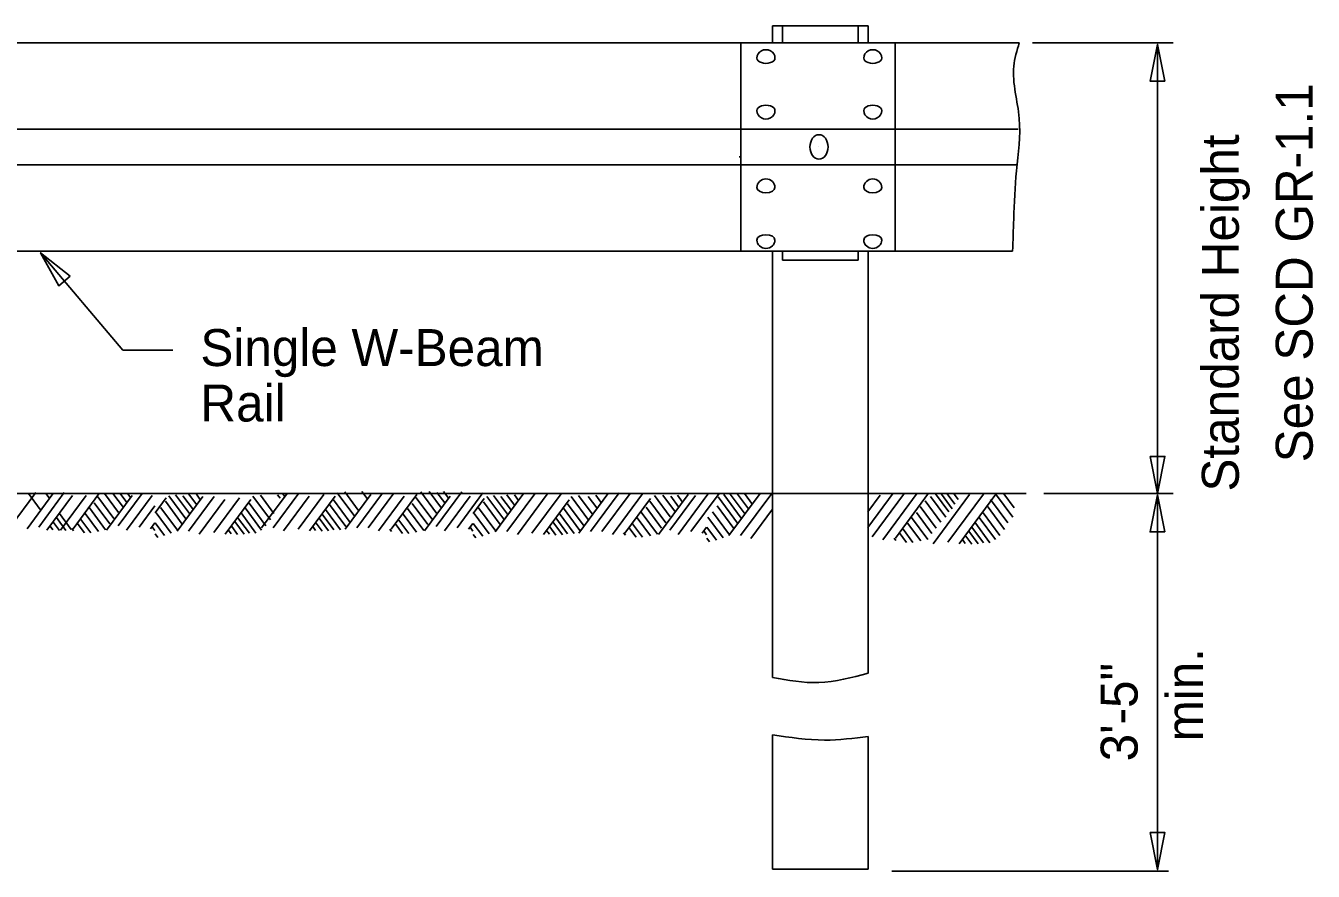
# Model space of a CAD drawing. Extents: x 0 to 34, y 0 to 22.
# Drawn here: x 18.561 to 23.437, y 8.943 to 12.146 of the extents above; entities that cross this region are included whole.
import ezdxf

# ---------------------------------------------------------------- set-up
doc = ezdxf.new("R2010")
doc.units = 0
doc.layers.add('ST_Details', color=7, linetype='Continuous')
doc.layers.add('ST_Text', color=7, linetype='Continuous')

msp = doc.modelspace()

# ---------------------------------------------------------------- linework, layer by layer
at = {"layer": 'ST_Details'}
for p, q in [((21.3896, 12.1461), (21.752, 12.1461)), ((21.3896, 12.0829), (21.3896, 12.1461)), ((21.4275, 12.1461), (21.4275, 12.0817)), ((21.7132, 12.1461), (21.7132, 12.0837)), ((21.752, 12.0837), (21.752, 12.1461)), ((14.5458, 12.0817), (21.8542, 12.0817)), ((21.2687, 11.2925), (21.2687, 12.0817)), ((21.8542, 11.2925), (21.8542, 12.0817)), ((21.8542, 12.0817), (22.3238, 12.0817)), ((15.1987, 11.7547), (21.2687, 11.7547)), ((21.2672, 11.7547), (22.3191, 11.7547)), ((21.5651, 11.687), (21.5651, 11.687)), ((15.1987, 11.6192), (21.2687, 11.6192)), ((21.2665, 11.6492), (21.2626, 11.6492)), ((21.2672, 11.6192), (22.3147, 11.6192)), ((15.1987, 11.2925), (21.8542, 11.2925)), ((21.3896, 11.2928), (21.3896, 10.3748)), ((21.4275, 11.2925), (21.4275, 11.2581)), ((21.7132, 11.2925), (21.7132, 11.2581)), ((21.752, 11.2925), (21.752, 10.3748)), ((21.8542, 11.2925), (22.2984, 11.2925)), ((21.4275, 11.2581), (21.7132, 11.2581)), ((21.752, 10.3748), (18.3908, 10.3748)), ((18.5023, 10.2463), (18.5994, 10.3778)), ((18.5661, 10.241), (18.6631, 10.3724)), ((18.6155, 10.3138), (18.5706, 10.3748)), ((18.6097, 10.2463), (18.7067, 10.3778)), ((18.6492, 10.3579), (18.6369, 10.3748)), ((18.6409, 10.2356), (18.7382, 10.3671)), ((18.6927, 10.2356), (18.7899, 10.3671)), ((18.7402, 10.241), (18.8374, 10.3724)), ((18.8788, 10.2594), (18.8202, 10.3388)), ((18.8949, 10.2796), (18.8342, 10.3617)), ((18.912, 10.3025), (18.8586, 10.3748)), ((18.867, 10.2356), (18.9641, 10.3671)), ((18.931, 10.3207), (18.891, 10.3748)), ((18.9106, 10.2518), (19.0014, 10.3748)), ((18.9431, 10.3406), (18.9179, 10.3748)), ((18.9422, 10.2356), (19.0392, 10.3671)), ((18.9585, 10.3579), (18.946, 10.3748)), ((19.0509, 10.3007), (19.0928, 10.3573)), ((19.1531, 10.2587), (19.0897, 10.3448)), ((19.1667, 10.2787), (19.1024, 10.3658)), ((19.1807, 10.2979), (19.1277, 10.3695)), ((19.1343, 10.2312), (19.2313, 10.3627)), ((19.1955, 10.3122), (19.1561, 10.3658)), ((19.1778, 10.2312), (19.275, 10.3627)), ((19.2075, 10.3324), (19.1785, 10.3715)), ((19.2229, 10.3496), (19.2069, 10.3715)), ((19.2175, 10.2206), (19.3146, 10.3519)), ((19.2728, 10.2261), (19.3699, 10.3573)), ((19.3165, 10.2206), (19.4135, 10.3519)), ((19.4878, 10.274), (19.4214, 10.3638)), ((19.5004, 10.2989), (19.4496, 10.3677)), ((19.454, 10.244), (19.5505, 10.3748)), ((19.4975, 10.244), (19.5947, 10.3754)), ((19.5241, 10.3567), (19.5145, 10.3695)), ((19.5426, 10.3623), (19.5334, 10.3748)), ((19.537, 10.2333), (19.6342, 10.3647)), ((19.5927, 10.2387), (19.6896, 10.3702)), ((19.636, 10.2333), (19.7332, 10.3647)), ((19.7897, 10.2647), (19.727, 10.3497)), ((19.8074, 10.2867), (19.7409, 10.3767)), ((19.8202, 10.3117), (19.7692, 10.3805)), ((19.7707, 10.2387), (19.8677, 10.3702)), ((19.8143, 10.244), (19.9114, 10.3754)), ((19.8539, 10.3557), (19.8342, 10.3823)), ((19.8579, 10.244), (19.9549, 10.3754)), ((19.8974, 10.2333), (19.9945, 10.3647)), ((19.9449, 10.2387), (20.042, 10.3702)), ((20.0997, 10.2772), (20.0387, 10.3595)), ((20.1167, 10.3002), (20.0571, 10.3805)), ((20.0717, 10.2333), (20.1687, 10.3647)), ((20.1357, 10.3183), (20.0884, 10.3823)), ((20.1153, 10.2493), (20.2122, 10.3808)), ((20.1477, 10.3383), (20.118, 10.3785)), ((20.1632, 10.3557), (20.1433, 10.3823)), ((20.147, 10.2333), (20.2439, 10.3647)), ((20.1943, 10.244), (20.2925, 10.3767)), ((20.2554, 10.2982), (20.2974, 10.3551)), ((20.3577, 10.2565), (20.2942, 10.3424)), ((20.3713, 10.2765), (20.3071, 10.3635)), ((20.3852, 10.2956), (20.3325, 10.3672)), ((20.3389, 10.2289), (20.4477, 10.3761)), ((20.3395, 10.2297), (20.4359, 10.3603)), ((20.4001, 10.3099), (20.3607, 10.3635)), ((20.3831, 10.2297), (20.4885, 10.3724)), ((20.4122, 10.3301), (20.3832, 10.3692)), ((20.4276, 10.3472), (20.4114, 10.3692)), ((20.4227, 10.219), (20.5352, 10.3713)), ((20.4782, 10.2245), (20.5881, 10.3734)), ((20.5215, 10.219), (20.6187, 10.3503)), ((20.693, 10.2724), (20.6266, 10.3623)), ((20.7057, 10.2973), (20.6547, 10.3662)), ((20.6562, 10.2245), (20.7657, 10.3726)), ((20.7237, 10.3195), (20.6915, 10.3631)), ((20.6999, 10.2297), (20.8087, 10.377)), ((20.7394, 10.3413), (20.7197, 10.368)), ((20.7433, 10.2297), (20.8499, 10.3738)), ((20.7829, 10.219), (20.8963, 10.3724)), ((20.8304, 10.2245), (20.9275, 10.3557)), ((20.9851, 10.2628), (20.9245, 10.3452)), ((21.0021, 10.2857), (20.9427, 10.3662)), ((20.9572, 10.219), (21.0695, 10.371)), ((21.0212, 10.304), (20.9738, 10.368)), ((21.0007, 10.2351), (21.0977, 10.3665)), ((21.0331, 10.3241), (21.0035, 10.3642)), ((21.0487, 10.3413), (21.0289, 10.368)), ((21.0324, 10.219), (21.1448, 10.3712)), ((21.0799, 10.2297), (21.1869, 10.3747)), ((21.2568, 10.2622), (21.1834, 10.3615)), ((21.2707, 10.2813), (21.2051, 10.3704)), ((21.2244, 10.2146), (21.3427, 10.3748)), ((21.2857, 10.2956), (21.229, 10.3722)), ((21.2977, 10.3157), (21.256, 10.372)), ((21.2678, 10.2146), (21.3862, 10.3748)), ((21.3131, 10.3329), (21.283, 10.3737)), ((21.3896, 10.3748), (21.3896, 9.6772)), ((21.7501, 10.2455), (21.8457, 10.375)), ((21.7501, 10.3042), (21.7972, 10.3679)), ((21.752, 10.3748), (21.752, 9.694)), ((22.3497, 10.3748), (21.752, 10.3748)), ((21.7673, 10.21), (21.8893, 10.3752)), ((21.807, 10.1993), (21.9372, 10.3756)), ((21.8545, 10.2047), (21.9804, 10.3753)), ((22.0262, 10.2662), (21.9669, 10.3466)), ((22.0452, 10.2843), (21.9873, 10.3627)), ((21.9977, 10.1842), (22.1357, 10.371)), ((22.0572, 10.3043), (22.0067, 10.3727)), ((22.0703, 10.3161), (22.0293, 10.3713)), ((22.0797, 10.3337), (22.0507, 10.3731)), ((22.0532, 10.1897), (22.1881, 10.3723)), ((22.0918, 10.3516), (22.0747, 10.3752)), ((22.0966, 10.1842), (22.2347, 10.3712)), ((22.2805, 10.2626), (22.2152, 10.3511)), ((22.2991, 10.2843), (22.2337, 10.3727)), ((22.3042, 10.3205), (22.2654, 10.3729)), ((18.7325, 10.2384), (18.688, 10.2987)), ((18.8365, 10.2309), (18.7863, 10.2987)), ((18.8633, 10.2366), (18.8019, 10.3196)), ((18.9898, 10.2463), (19.0497, 10.3275)), ((19.1116, 10.2234), (19.0543, 10.3008)), ((19.1362, 10.2339), (19.0714, 10.3217)), ((19.4326, 10.2243), (19.3762, 10.3008)), ((19.4539, 10.2357), (19.3917, 10.3198)), ((19.4701, 10.252), (19.4073, 10.3371)), ((19.7277, 10.2362), (19.6832, 10.2963)), ((19.7525, 10.237), (19.6958, 10.3135)), ((19.7735, 10.2487), (19.7114, 10.3326)), ((20.0411, 10.2284), (19.9909, 10.2963)), ((20.068, 10.2342), (20.0065, 10.3173)), ((20.0835, 10.2572), (20.0247, 10.3365)), ((20.3162, 10.221), (20.259, 10.2985)), ((20.3409, 10.2316), (20.276, 10.3195)), ((20.638, 10.2227), (20.5813, 10.2992)), ((20.659, 10.2342), (20.5971, 10.3183)), ((20.6753, 10.2504), (20.6125, 10.3355)), ((20.9533, 10.2199), (20.8919, 10.3031)), ((20.9689, 10.2427), (20.9105, 10.3221)), ((21.2264, 10.2172), (21.1615, 10.3052)), ((21.2433, 10.2422), (21.1797, 10.328)), ((21.3077, 10.2038), (21.3896, 10.3148)), ((21.993, 10.2232), (21.9344, 10.3025)), ((22.0092, 10.2433), (21.9486, 10.3255)), ((22.2502, 10.2157), (22.1875, 10.3008)), ((22.2679, 10.2377), (22.2017, 10.3275)), ((18.6634, 10.2366), (18.6527, 10.2508)), ((18.688, 10.2337), (18.6654, 10.2643)), ((18.7128, 10.2346), (18.6767, 10.2834)), ((18.742, 10.2326), (18.7353, 10.2413)), ((18.7827, 10.225), (18.7552, 10.2623)), ((18.8067, 10.225), (18.7694, 10.2757)), ((19.0334, 10.241), (19.0497, 10.2632)), ((19.0497, 10.2344), (19.0389, 10.2489)), ((19.0868, 10.2147), (19.0509, 10.2635)), ((19.3634, 10.2186), (19.3409, 10.2492)), ((19.3882, 10.2196), (19.3522, 10.2683)), ((19.4081, 10.2234), (19.3634, 10.2836)), ((19.6584, 10.2342), (19.6479, 10.2487)), ((19.6832, 10.2314), (19.6606, 10.2619)), ((19.7078, 10.2323), (19.6717, 10.281)), ((19.9874, 10.2227), (19.9598, 10.26)), ((20.0114, 10.2227), (19.9741, 10.2733)), ((20.238, 10.2387), (20.2542, 10.261)), ((20.2542, 10.2322), (20.2436, 10.2467)), ((20.2915, 10.2124), (20.2554, 10.2612)), ((20.5686, 10.217), (20.546, 10.2476)), ((20.5933, 10.2181), (20.5574, 10.2667)), ((20.6131, 10.2218), (20.5686, 10.282)), ((20.8729, 10.2084), (20.8453, 10.2457)), ((20.8969, 10.2084), (20.8595, 10.2591)), ((20.9266, 10.2142), (20.8765, 10.282)), ((21.1234, 10.2245), (21.1398, 10.2467)), ((21.177, 10.1981), (21.141, 10.2469)), ((21.2017, 10.2067), (21.1444, 10.2842)), ((21.9507, 10.1947), (21.9005, 10.2624)), ((21.9777, 10.2003), (21.9161, 10.2834)), ((22.1882, 10.1872), (22.1442, 10.2467)), ((22.2129, 10.188), (22.1556, 10.2656)), ((22.2341, 10.1994), (22.1719, 10.2836)), ((19.0608, 10.208), (19.0509, 10.2215)), ((19.3387, 10.2215), (19.3282, 10.2357)), ((19.9467, 10.2302), (19.94, 10.2389)), ((20.2654, 10.2057), (20.2554, 10.219)), ((20.5441, 10.2199), (20.5334, 10.2342)), ((20.832, 10.2158), (20.8254, 10.2247)), ((21.1398, 10.2179), (21.1291, 10.2323)), ((21.1509, 10.1915), (21.141, 10.2047)), ((21.8561, 10.1963), (21.8496, 10.2051)), ((21.8969, 10.1887), (21.8694, 10.2261)), ((21.9209, 10.1887), (21.8835, 10.2394)), ((22.119, 10.1852), (22.1084, 10.1994)), ((22.1436, 10.1822), (22.1211, 10.2128)), ((22.1685, 10.1833), (22.1323, 10.2322)), ((21.3894, 9.4602), (21.3894, 9.4539)), ((21.3894, 9.4538), (21.3894, 8.9514)), ((21.752, 9.4544), (21.752, 8.9514)), ((21.3894, 8.9514), (21.752, 8.9514))]:
    msp.add_line(p, q, dxfattribs=at)
for centre, major_axis, ratio, start_param, end_param in [((21.3644, 12.0238), (0.0342, 0), 0.920676, 0, 3.141593), ((21.769, 12.0238), (0.0342, 0), 0.920676, 0, 3.141593), ((21.3644, 12.0238), (-0.0342, 0), 0.587975, 0, 3.141593), ((21.769, 12.0238), (-0.0342, 0), 0.587975, 0, 3.141593), ((21.3644, 11.8247), (0.0342, 0), 0.599655, 0, 3.141593), ((21.3644, 11.8247), (-0.0342, 0), 0.943283, 0, 3.141593), ((21.769, 11.8247), (0.0342, 0), 0.599655, 0, 3.141593), ((21.769, 11.8247), (-0.0342, 0), 0.943283, 0, 3.141593), ((21.3644, 11.5335), (-0.0342, 0), 0.943283, 3.141593, 6.283185), ((21.769, 11.5335), (-0.0342, 0), 0.943283, 3.141593, 6.283185), ((21.3644, 11.5335), (0.0342, 0), 0.599655, 3.141593, 6.283185), ((21.769, 11.5335), (0.0342, 0), 0.599655, 3.141593, 6.283185), ((21.3644, 11.3344), (-0.0342, 0), 0.587975, 3.141593, 6.283185), ((21.3644, 11.3344), (0.0342, 0), 0.920676, 3.141593, 6.283185), ((21.769, 11.3344), (-0.0342, 0), 0.587975, 3.141593, 6.283185), ((21.769, 11.3344), (0.0342, 0), 0.920676, 3.141593, 6.283185)]:
    msp.add_ellipse(centre, major_axis=major_axis, ratio=ratio, start_param=start_param, end_param=end_param, dxfattribs=at)
msp.add_ellipse((21.5653, 11.6871), major_axis=(0, 0.0463), ratio=0.738563, dxfattribs=at)
for points in [[(22.2984, 11.292), (22.303, 11.4133), (22.3134, 11.5969), (22.3238, 11.7947), (22.303, 11.9925), (22.3238, 12.0817)], [(21.752, 9.694), (21.5642, 9.658), (21.3896, 9.6772)], [(21.752, 9.4544), (21.5864, 9.4401), (21.3894, 9.4602)]]:
    msp.add_spline(points, degree=3, dxfattribs=at)
at = {"layer": 'ST_Text'}
for p, q in [((22.3736, 12.0817), (22.9066, 12.0817)), ((22.8477, 12.0756), (22.8477, 11.2863)), ((22.8477, 11.2863), (22.8477, 10.3748)), ((22.417, 10.3748), (22.9066, 10.3748)), ((22.8475, 10.3687), (22.8475, 8.9495)), ((21.8417, 8.9433), (22.8896, 8.9433))]:
    msp.add_line(p, q, dxfattribs=at)
for points in [[(22.8757, 11.9356), (22.8197, 11.9356), (22.8477, 12.0756)], [(18.7285, 11.1971), (18.6857, 11.161), (18.6167, 11.286)], [(22.8197, 10.5148), (22.8757, 10.5148), (22.8477, 10.3748)], [(22.8755, 10.2287), (22.8195, 10.2287), (22.8475, 10.3687)], [(22.8195, 9.0895), (22.8755, 9.0895), (22.8475, 8.9495)]]:
    msp.add_lwpolyline(points, close=True, dxfattribs=at)
msp.add_lwpolyline([(18.6167, 11.286), (18.9287, 10.9166), (19.1182, 10.9166)], dxfattribs=at)

# ---------------------------------------------------------------- texts
for s, p in [('See SCD GR-1.1', (23.4354, 10.4924)), ('Standard Height', (23.1554, 10.3816)), ('min.', (23.0202, 9.4352)), ('3\'-5"', (22.7722, 9.3597))]:
    msp.add_text(s, height=0.14, rotation=90, dxfattribs=at).set_placement(p)
for s, p in [('Single W-Beam', (19.2223, 10.857)), ('Rail', (19.2223, 10.647))]:
    msp.add_text(s, height=0.14, dxfattribs=at).set_placement(p)

doc.saveas('drawing.dxf')
